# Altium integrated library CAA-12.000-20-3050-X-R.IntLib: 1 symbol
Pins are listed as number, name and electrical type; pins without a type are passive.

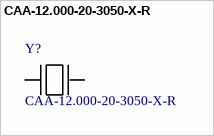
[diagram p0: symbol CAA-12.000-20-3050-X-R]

## CAA-12.000-20-3050-X-R
designator Y?
12 MHz Â±30ppm Crystal 20pF 50 Ohms HC-49/US; MF: Aker Technology Corp
footprint *XTAL_CAA-12.000-20-3050-X-R
pins: 1, 2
